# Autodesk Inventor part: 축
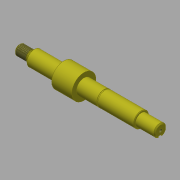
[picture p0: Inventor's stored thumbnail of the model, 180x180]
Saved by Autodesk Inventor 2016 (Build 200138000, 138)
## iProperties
Created: 2016-08
Part Number: 축
Material: 강철, 탄소
Document SubType Name: Modeling
Designer: mduedu
Density: 7.87 g/cm^3
Appearance: 밝은 황색
Author: mduedu
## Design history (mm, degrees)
sketch "스케치1"
  geometry: L1 (-70, 0)-(70, 0); L2 (-70, 0)-(-70, 5); L3 (-70, 5)-(-56, 5); L4 (-56, 5)-(-56, 7.5); L5 (-56, 7.5)-(51, 7.5); L6 (51, 7.5)-(51, 6); L7 (51, 6)-(70, 6); L8 (70, 6)-(70, 0); 2 further points
  constraints: 16 end point, 5 parallel, 2 perpendicular, 1 coincident, 1 horizontal, 1 midpoint
  dimensions: "d0" = 140 distance of L1.start L1.end; "d2" = 14 distance of L2.end L3.end; "d3" = 19 distance of L6.end L7.end; "d4" = 10 diameter of L3 L1; "d5" = 15 diameter of L5 L1; "d6" = 12 diameter of L7 L1
revolve "회전1" sketch "스케치1" stored, may be unused: angle "d7" = 90 deg
sketch "스케치2"
  geometry: L1 (-56, -5)-(-56, 5) reference; L2 (70, -6)-(70, 6) reference; L3 (-56, 0)-(70, 0); L4 (-58, 4.5)-(-58, 5); L5 (-58, 5)-(-56, 5); L6 (-56, 5)-(-56, 4.5); L7 (-58, 4.5)-(-56, 4.5); 1 further point
  constraints: 10 end point, 2 midpoint, 1 parallel, 1 perpendicular, 1 point on line
  dimensions: "d8" = 2 distance of L4.end L5.end; "d10" = 10 diameter of L5 L3; "d11" = 9 diameter of L7 L3
revolve "회전2" sketch "스케치2" stored, may be unused: angle "d12" = 90 deg
node "작업 평면1"
sketch "스케치3"
  geometry: C1 r 12 at (0, 0); 1 further point
  constraints: 1 centre point, 1 coincident
  dimensions: "d15" = 24 diameter of C1
extrude "돌출1" join sketch "스케치3" distance "d16" = 20; taper "d17" = 0 deg
sketch "스케치5"
  geometry: L1 (-70, -5)-(-70, 5) reference; L2 (70, -6)-(70, 6) reference; L3 (-70, 0)-(70, 0); L4 (-6, 7.5)-(51, 7.5) reference; L5 (15.15, 7.5)-(14, 7.5); L6 (14, 7.5)-(14, 7.15); L7 (14, 7.15)-(15.15, 7.15); L8 (15.15, 7.15)-(15.15, 7.5); 1 further point
  constraints: 10 end point, 2 midpoint, 2 parallel, 1 horizontal, 1 perpendicular, 1 point on line
  dimensions: "d19" = 56 distance between parallel lines of L6 L2; "d20" = 1.15 distance between parallel lines of L8 L6; "d21" = 14.3 diameter of L7 L3
revolve "회전3" sketch "스케치5" stored, may be unused: angle "d22" = 90 deg
node "작업 평면3"
sketch "스케치6"
  geometry: L1 (6.5, 2)-(-9.5, 2); L2 (-9.5, 2)-(-9.5, -2); L3 (-9.5, -2)-(6.5, -2); L4 (-9.5, 6)-(-9.5, -6) reference; A1 r 2 centre (6.5, 0) between (6.5, -2) and (6.5, 2); 2 further points
  constraints: 6 end point, 2 midpoint, 2 point on circle, 2 tangent, 1 centre point, 1 horizontal, 1 horizontal alignment, 1 parallel, 1 perpendicular
  dimensions: "d23" = 4 distance between parallel lines of L3 L1; "d62" = 18 dimension on A1 L2
extrude "돌출2" cut sketch "스케치6" distance "d25" = 2.5; taper "d26" = 0 deg
feature "스레드1" dims "d27" = 10, "d28" = 0
chamfer "모따기5" distance "d41" = 0.5; stored, may be unused: second distance "d42" = 2, angle "d43" = 45 deg
chamfer "모따기6" distance "d44" = 0.5; stored, may be unused: second distance "d45" = 2, angle "d46" = 45 deg
chamfer "모따기7" distance "d47" = 1; stored, may be unused: second distance "d48" = 2, angle "d49" = 45 deg
chamfer "모따기8" distance "d50" = 1; stored, may be unused: second distance "d51" = 2, angle "d52" = 45 deg
sketch "스케치8"
  geometry: 1 further point
hole "구멍1" sketch "스케치8" at (2, 3.5) diameter "d53" = 3.242; stored, may be unused: countersink angle "d57" = 90 deg, drill point angle "d59" = 120 deg; dims "d54" = 10, "d55" = 4, "d56" = 2, "d58" = 12
node "솔리드1"
other parameters: "d13" = -44
